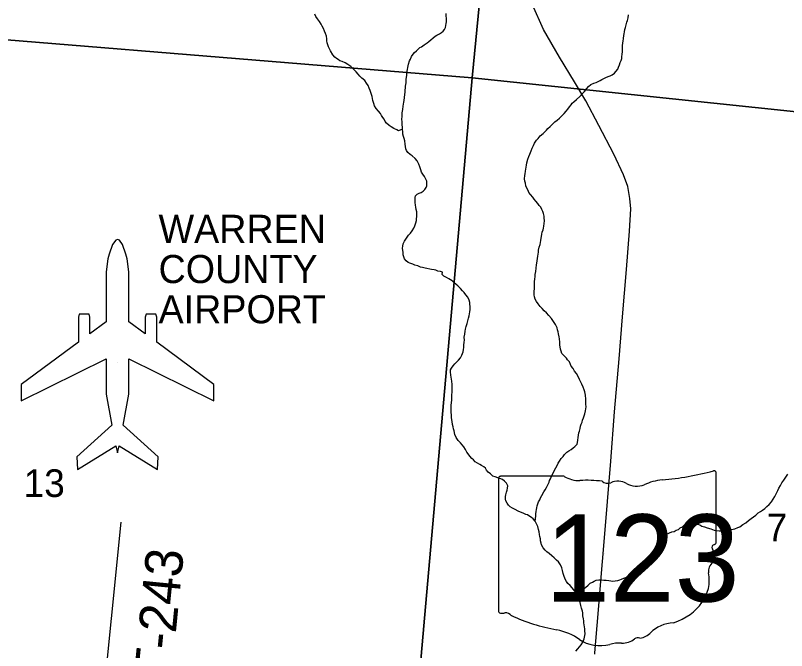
# Model space of a CAD drawing. Extents: x 0 to 1064, y 0 to 440.
# Drawn here: x 203.09 to 221.76, y 263.3 to 278.69 of the extents above; entities that cross this region are included whole.
import ezdxf

# ---------------------------------------------------------------- set-up
doc = ezdxf.new("R2010")
doc.units = 0
for name, color, linetype in [('GM_X_Airport_Class_2', 7, 'Continuous'), ('GM_X_Airport_Location_Class_2', 7, 'Continuous'), ('GM_X_Airport_Text_Class_2', 7, 'Continuous'), ('GM_X_Minor_River', 7, 'Continuous'), ('GM_X_Section', 7, 'Continuous'), ('GM_X_Section_Text', 7, 'Continuous'), ('GM_X_State_Location', 7, 'Continuous'), ('GM_X_State_Route', 7, 'Continuous'), ('GM_X_State_Shield', 7, 'Continuous'), ('GM_X_Township_Road', 7, 'Continuous'), ('GM_X_Township_Road_Text', 7, 'Continuous')]:
    doc.layers.add(name, color=color, linetype=linetype)

msp = doc.modelspace()

# ---------------------------------------------------------------- linework, layer by layer
at = {"layer": 'GM_X_Airport_Class_2'}
msp.add_lwpolyline([(204.616, 270.769), (203.233, 269.747), (203.233, 269.354), (205.29, 270.368), (205.29, 269.514), (205.427, 268.759), (204.58, 267.999), (204.594, 267.686), (205.521, 268.261), (205.564, 268.093), (205.606, 268.261), (206.534, 267.686), (206.547, 267.999), (205.7, 268.759), (205.837, 269.514), (205.837, 270.368), (207.895, 269.354), (207.895, 269.747), (206.512, 270.769), (206.512, 271.38), (206.49, 271.454), (206.255, 271.454), (206.233, 271.38), (206.233, 270.975), (205.837, 271.268), (205.837, 271.268), (205.837, 272.474), (205.797, 272.793), (205.764, 272.906), (205.682, 273.138), (205.607, 273.242), (205.564, 273.26), (205.521, 273.242), (205.445, 273.138), (205.363, 272.906), (205.33, 272.793), (205.29, 272.474), (205.29, 271.268), (204.894, 270.975), (204.894, 271.38), (204.873, 271.454), (204.637, 271.454), (204.616, 271.38)], close=True, dxfattribs=at)
at = {"layer": 'GM_X_Airport_Location_Class_2'}
msp.add_line((205.564, 270.282), (205.564, 270.282), dxfattribs=at)
at = {"layer": 'GM_X_Minor_River'}
for points in [[(212.462, 275.927), (212.364, 275.888), (212.322, 275.913), (212.25, 275.946), (212.184, 275.99), (212.137, 276.016), (212.078, 276.073), (212.042, 276.116), (212.014, 276.172), (211.985, 276.215), (211.956, 276.265), (211.927, 276.314), (211.88, 276.37), (211.828, 276.432), (211.787, 276.494), (211.765, 276.55), (211.743, 276.623), (211.732, 276.672), (211.728, 276.721), (211.706, 276.794), (211.678, 276.868), (211.655, 276.923), (211.633, 276.985), (211.592, 277.047), (211.546, 277.109), (211.48, 277.166), (211.427, 277.216), (211.392, 277.259), (211.339, 277.322), (211.28, 277.378), (211.21, 277.447), (211.138, 277.498), (211.073, 277.536), (211.001, 277.569), (210.946, 277.589), (210.905, 277.62), (210.863, 277.646), (210.821, 277.678), (210.774, 277.728), (210.717, 277.827), (210.671, 277.925), (210.655, 277.974), (210.638, 278.023), (210.633, 278.066), (210.629, 278.121), (210.619, 278.182), (210.597, 278.249), (210.574, 278.305), (210.552, 278.372), (210.517, 278.422), (210.495, 278.471), (210.454, 278.539), (210.401, 278.601), (210.367, 278.657), (210.338, 278.712)], [(212.809, 273.871), (212.805, 273.931), (212.794, 273.986), (212.784, 274.041), (212.773, 274.09), (212.769, 274.151), (212.765, 274.2), (212.767, 274.273), (212.775, 274.315), (212.819, 274.356), (212.868, 274.379), (212.917, 274.401), (212.961, 274.431), (213.005, 274.472), (213.031, 274.519), (213.051, 274.561), (213.047, 274.628), (213.048, 274.671), (213.02, 274.738), (212.997, 274.788), (212.95, 274.838), (212.921, 274.893), (212.905, 274.948), (212.883, 275.022), (212.855, 275.083), (212.815, 275.164), (212.768, 275.22), (212.697, 275.283), (212.649, 275.314), (212.59, 275.365), (212.555, 275.414), (212.544, 275.457), (212.534, 275.512), (212.524, 275.567), (212.514, 275.646), (212.504, 275.707), (212.487, 275.75), (212.471, 275.812), (212.467, 275.866), (212.462, 275.927), (212.458, 275.976), (212.454, 276.037), (212.45, 276.11), (212.446, 276.171), (212.454, 276.237), (212.456, 276.286), (212.457, 276.328), (212.466, 276.407), (212.481, 276.485), (212.489, 276.54), (212.49, 276.582), (212.498, 276.624), (212.506, 276.697), (212.515, 276.769), (212.522, 276.824), (212.524, 276.884), (212.532, 276.927), (212.533, 276.969), (212.541, 277.011), (212.548, 277.054), (212.55, 277.096), (212.551, 277.139), (212.559, 277.181), (212.567, 277.235), (212.568, 277.284), (212.576, 277.332), (212.583, 277.374), (212.591, 277.423), (212.598, 277.465), (212.606, 277.507), (212.633, 277.585), (212.653, 277.627), (212.679, 277.687), (212.723, 277.746), (212.755, 277.788), (212.799, 277.829), (212.837, 277.87), (212.881, 277.906), (212.924, 277.928), (212.987, 277.969), (213.055, 278.022), (213.099, 278.057), (213.149, 278.098), (213.205, 278.144), (213.249, 278.179), (213.293, 278.208), (213.355, 278.237), (213.404, 278.272), (213.448, 278.301), (213.48, 278.348), (213.5, 278.396), (213.514, 278.445), (213.515, 278.487), (213.523, 278.529), (213.525, 278.602), (213.521, 278.681), (213.517, 278.73)], [(217.629, 277.328), (217.674, 277.381), (217.694, 277.435), (217.714, 277.489), (217.728, 277.543), (217.754, 277.597), (217.768, 277.645), (217.775, 277.688), (217.777, 277.736), (217.785, 277.809), (217.788, 277.888), (217.79, 277.948), (217.798, 278.021), (217.8, 278.063), (217.814, 278.124), (217.822, 278.196), (217.83, 278.238), (217.838, 278.287), (217.846, 278.341), (217.859, 278.395), (217.874, 278.456), (217.894, 278.522), (217.908, 278.564), (217.922, 278.63), (217.93, 278.697)], [(215.653, 272.059), (215.655, 272.119), (215.657, 272.186), (215.659, 272.247), (215.667, 272.289), (215.675, 272.368), (215.677, 272.41), (215.691, 272.482), (215.7, 272.567), (215.709, 272.646), (215.71, 272.688), (215.724, 272.742), (215.726, 272.797), (215.734, 272.858), (215.742, 272.906), (215.75, 272.954), (215.757, 273.003), (215.772, 273.075), (215.792, 273.141), (215.806, 273.183), (215.814, 273.238), (215.822, 273.292), (215.829, 273.334), (215.837, 273.389), (215.845, 273.437), (215.865, 273.491), (215.872, 273.533), (215.88, 273.582), (215.894, 273.648), (215.897, 273.715), (215.893, 273.781), (215.888, 273.824), (215.878, 273.885), (215.861, 273.94), (215.832, 273.984), (215.81, 274.045), (215.769, 274.083), (215.734, 274.132), (215.687, 274.189), (215.652, 274.232), (215.617, 274.288), (215.564, 274.35), (215.523, 274.4), (215.5, 274.443), (215.472, 274.499), (215.45, 274.56), (215.439, 274.621), (215.423, 274.67), (215.418, 274.725), (215.421, 274.81), (215.429, 274.852), (215.437, 274.913), (215.444, 274.961), (215.458, 275.009), (215.466, 275.063), (215.474, 275.118), (215.495, 275.202), (215.516, 275.268), (215.542, 275.328), (215.575, 275.406), (215.601, 275.472), (215.634, 275.538), (215.66, 275.592), (215.705, 275.663), (215.743, 275.705), (215.794, 275.77), (215.869, 275.828), (215.945, 275.905), (215.982, 275.946), (216.039, 275.999), (216.089, 276.052), (216.152, 276.105), (216.208, 276.152), (216.265, 276.198), (216.315, 276.251), (216.372, 276.31), (216.423, 276.37), (216.461, 276.417), (216.505, 276.47), (216.543, 276.518), (216.569, 276.559), (216.613, 276.594), (216.676, 276.653), (216.751, 276.724), (216.82, 276.794), (216.864, 276.842), (216.922, 276.913), (216.966, 276.96), (217.022, 277.013), (217.096, 277.047), (217.152, 277.063), (217.195, 277.086), (217.245, 277.109), (217.288, 277.132), (217.338, 277.161), (217.387, 277.184), (217.443, 277.206), (217.492, 277.223), (217.535, 277.246), (217.591, 277.287), (217.629, 277.328)], [(213.651, 268.945), (213.647, 269.018), (213.636, 269.061), (213.638, 269.116), (213.64, 269.176), (213.642, 269.243), (213.644, 269.31), (213.652, 269.37), (213.655, 269.437), (213.657, 269.498), (213.665, 269.564), (213.667, 269.631), (213.664, 269.704), (213.665, 269.746), (213.655, 269.825), (213.651, 269.88), (213.641, 269.929), (213.63, 269.972), (213.62, 270.051), (213.622, 270.106), (213.648, 270.147), (213.692, 270.201), (213.73, 270.248), (213.774, 270.295), (213.818, 270.336), (213.863, 270.396), (213.901, 270.455), (213.915, 270.497), (213.929, 270.54), (213.936, 270.594), (213.944, 270.642), (213.946, 270.697), (213.955, 270.775), (213.962, 270.824), (213.958, 270.891), (213.967, 270.969), (213.975, 271.036), (213.989, 271.084), (214.004, 271.15), (214.024, 271.223), (214.045, 271.289), (214.059, 271.355), (214.073, 271.409), (214.087, 271.457), (214.094, 271.506), (214.102, 271.56), (214.099, 271.639), (214.095, 271.694), (214.09, 271.737), (214.073, 271.786), (214.039, 271.86), (213.998, 271.915), (213.951, 271.972), (213.91, 272.015), (213.863, 272.071), (213.799, 272.134), (213.757, 272.172), (213.704, 272.216), (213.662, 272.254), (213.585, 272.305), (213.525, 272.337), (213.459, 272.369), (213.418, 272.413), (213.426, 272.467), (213.384, 272.481), (213.317, 272.495), (213.269, 272.515), (213.227, 272.522), (213.166, 272.536), (213.124, 272.543), (213.051, 272.558), (213.009, 272.565), (212.943, 272.579), (212.9, 272.593), (212.834, 272.619), (212.762, 272.64), (212.708, 272.66), (212.642, 272.686), (212.6, 272.705), (212.552, 272.743), (212.511, 272.793), (212.495, 272.842), (212.478, 272.891), (212.474, 272.952), (212.469, 272.995), (212.465, 273.05), (212.466, 273.098), (212.481, 273.158), (212.507, 273.218), (212.539, 273.266), (212.577, 273.319), (212.603, 273.361), (212.653, 273.414), (212.692, 273.467), (212.737, 273.533), (212.757, 273.587), (212.783, 273.659), (212.798, 273.719), (212.799, 273.768), (212.807, 273.81), (212.809, 273.871)], [(215.669, 266.436), (215.691, 266.563), (215.693, 266.618), (215.695, 266.672), (215.702, 266.721), (215.71, 266.763), (215.724, 266.811), (215.737, 266.859), (215.751, 266.907), (215.783, 266.955), (215.803, 267.003), (215.835, 267.063), (215.881, 267.146), (215.919, 267.194), (215.951, 267.253), (215.978, 267.319), (216.01, 267.379), (216.024, 267.421), (216.043, 267.463), (216.057, 267.505), (216.077, 267.547), (216.115, 267.619), (216.135, 267.66), (216.174, 267.726), (216.206, 267.786), (216.233, 267.846), (216.265, 267.893), (216.303, 267.953), (216.347, 268.006), (216.386, 268.053), (216.436, 268.106), (216.486, 268.141), (216.542, 268.176), (216.592, 268.217), (216.635, 268.246), (216.686, 268.299), (216.7, 268.347), (216.707, 268.396), (216.716, 268.462), (216.724, 268.517), (216.732, 268.577), (216.745, 268.619), (216.76, 268.685), (216.774, 268.74), (216.787, 268.788), (216.807, 268.836), (216.821, 268.884), (216.847, 268.944), (216.861, 268.992), (216.875, 269.04), (216.889, 269.112), (216.903, 269.161), (216.905, 269.203), (216.901, 269.27), (216.902, 269.312), (216.899, 269.391), (216.89, 269.489), (216.874, 269.568), (216.863, 269.617), (216.835, 269.685), (216.801, 269.759), (216.778, 269.802), (216.75, 269.87), (216.716, 269.943), (216.675, 270.012), (216.629, 270.074), (216.594, 270.135), (216.547, 270.192), (216.525, 270.235), (216.502, 270.296), (216.455, 270.346), (216.432, 270.389), (216.367, 270.446), (216.32, 270.502), (216.304, 270.551), (216.287, 270.6), (216.277, 270.661), (216.272, 270.704), (216.268, 270.771), (216.265, 270.856), (216.254, 270.905), (216.239, 270.978), (216.228, 271.027), (216.217, 271.07), (216.207, 271.119), (216.167, 271.199), (216.12, 271.273), (216.068, 271.348), (216.003, 271.416), (215.945, 271.485), (215.892, 271.535), (215.845, 271.585), (215.791, 271.636), (215.745, 271.698), (215.704, 271.754), (215.676, 271.815), (215.653, 271.87), (215.649, 271.919), (215.65, 271.968), (215.652, 272.016), (215.653, 272.059)], [(216.869, 263.88), (216.858, 263.928), (216.854, 263.977), (216.849, 264.026), (216.845, 264.069), (216.829, 264.148), (216.825, 264.215), (216.821, 264.258), (216.792, 264.331), (216.776, 264.392), (216.76, 264.466), (216.732, 264.539), (216.709, 264.583), (216.693, 264.638), (216.653, 264.718), (216.6, 264.78), (216.565, 264.824), (216.518, 264.88), (216.465, 264.93), (216.43, 264.98), (216.396, 265.036), (216.368, 265.121), (216.351, 265.171), (216.336, 265.244), (216.319, 265.305), (216.285, 265.379), (216.239, 265.453), (216.192, 265.497), (216.133, 265.554), (216.079, 265.598), (216.008, 265.655), (215.955, 265.699), (215.913, 265.737), (215.866, 265.793), (215.826, 265.861), (215.821, 265.903), (215.805, 265.959), (215.8, 266.007), (215.79, 266.068), (215.78, 266.117), (215.77, 266.178), (215.753, 266.239), (215.737, 266.307), (215.709, 266.374), (215.669, 266.436), (215.628, 266.498), (215.586, 266.53), (215.545, 266.555), (215.491, 266.594), (215.449, 266.601), (215.383, 266.633), (215.316, 266.654), (215.262, 266.68), (215.185, 266.718), (215.125, 266.751), (215.071, 266.789), (215.03, 266.826), (214.995, 266.876), (214.966, 266.932), (214.956, 266.974), (214.958, 267.035), (214.965, 267.077), (214.979, 267.144), (214.993, 267.192), (215.007, 267.24), (215.009, 267.295), (214.981, 267.362), (214.933, 267.406), (214.88, 267.444), (214.814, 267.471), (214.772, 267.49), (214.705, 267.51), (214.645, 267.53), (214.592, 267.581), (214.539, 267.625), (214.498, 267.675), (214.469, 267.718), (214.427, 267.756), (214.374, 267.788), (214.332, 267.807), (214.278, 267.839), (214.224, 267.877), (214.177, 267.921), (214.136, 267.959), (214.095, 268.009), (214.048, 268.065), (214.019, 268.108), (213.984, 268.17), (213.944, 268.238), (213.903, 268.288), (213.862, 268.332), (213.809, 268.394), (213.763, 268.462), (213.728, 268.536), (213.713, 268.622), (213.697, 268.677), (213.686, 268.72), (213.67, 268.781), (213.66, 268.848), (213.655, 268.891), (213.651, 268.945)], [(216.653, 264.718), (216.813, 264.762), (216.888, 264.832), (216.957, 264.891), (217.007, 264.938), (217.057, 264.961), (217.1, 264.984), (217.15, 265.006), (217.211, 265.017), (217.278, 265.021), (217.333, 265.013), (217.393, 265.011), (217.46, 265.003), (217.502, 264.995), (217.545, 264.988), (217.606, 264.992), (217.673, 265.002), (217.722, 265.019), (217.765, 265.03), (217.821, 265.058), (217.864, 265.075), (217.92, 265.104), (217.97, 265.133), (218.038, 265.167), (218.081, 265.196), (218.131, 265.225), (218.181, 265.26), (218.231, 265.301), (218.275, 265.336), (218.331, 265.371), (218.381, 265.411), (218.431, 265.459), (218.475, 265.494), (218.531, 265.546), (218.582, 265.612), (218.608, 265.666), (218.628, 265.72), (218.636, 265.78), (218.644, 265.828), (218.652, 265.871), (218.659, 265.919), (218.691, 265.967), (218.723, 266.014), (218.773, 266.055), (218.817, 266.09), (218.861, 266.125), (218.923, 266.154), (218.984, 266.176), (219.04, 266.186), (219.089, 266.221), (219.139, 266.238), (219.183, 266.273), (219.238, 266.302), (219.282, 266.343), (219.344, 266.377), (219.387, 266.388), (219.436, 266.393), (219.497, 266.391), (219.557, 266.377), (219.606, 266.363), (219.66, 266.349), (219.708, 266.318), (219.774, 266.303), (219.84, 266.277), (219.925, 266.25), (220.003, 266.224), (220.063, 266.216), (220.124, 266.208), (220.191, 266.206), (220.24, 266.204), (220.307, 266.214), (220.368, 266.218), (220.429, 266.235), (220.503, 266.251), (220.583, 266.285), (220.627, 266.301), (220.701, 266.354), (220.77, 266.394), (220.838, 266.453), (220.901, 266.505), (220.957, 266.546), (221.013, 266.587), (221.07, 266.64), (221.126, 266.675), (221.176, 266.703), (221.232, 266.744), (221.282, 266.791), (221.339, 266.844), (221.395, 266.909), (221.434, 266.969), (221.473, 267.034), (221.505, 267.1), (221.544, 267.178), (221.571, 267.238), (221.609, 267.303), (221.642, 267.369), (221.693, 267.428), (221.738, 267.5), (221.789, 267.577)], [(216.661, 263.291), (216.705, 263.344), (216.743, 263.392), (216.788, 263.445), (216.826, 263.511), (216.859, 263.588), (216.874, 263.667), (216.882, 263.709), (216.878, 263.782), (216.873, 263.831), (216.869, 263.88)]]:
    msp.add_lwpolyline(points, dxfattribs=at)
at = {"layer": 'GM_X_Section'}
for points in [[(215.966, 295.854), (214.149, 277.17), (197.538, 278.526), (198.919, 293.248)], [(232.294, 291.87), (230.695, 275.436), (214.149, 277.17), (215.966, 295.854)], [(214.149, 277.17), (212.38, 257.134), (197.008, 258.503), (195.61, 258.628), (197.538, 278.526)], [(230.695, 275.436), (228.85, 255.88), (213.239, 257.045), (212.38, 257.134), (214.149, 277.17)]]:
    msp.add_lwpolyline(points, close=True, dxfattribs=at)
at = {"layer": 'GM_X_State_Route'}
msp.add_lwpolyline([(217.117, 263.217), (217.119, 263.247), (217.196, 264.193), (217.263, 264.982), (217.34, 265.935), (217.424, 266.911), (217.501, 267.888), (217.596, 269.083), (217.705, 270.369), (217.79, 271.388), (217.884, 272.535), (217.96, 273.463), (217.991, 274.003), (217.967, 274.253), (217.919, 274.546), (217.81, 274.828), (217.578, 275.326), (217.217, 276.021), (216.896, 276.618), (216.627, 277.074), (216.263, 277.672), (215.877, 278.344), (215.61, 278.945)], dxfattribs=at)
at = {"layer": 'GM_X_State_Shield'}
for p, q in [((216.378, 267.524), (214.834, 267.524)), ((220.055, 265.928), (220.055, 267.603)), ((214.782, 267.468), (214.782, 264.267)), ((220.055, 265.928), (220.055, 265.928))]:
    msp.add_line(p, q, dxfattribs=at)
for centre, major_axis, start_param, end_param in [((214.842, 267.475), (0.0611, 0), 1.712693, 3.28349), ((216.746, 267.895), (0.593, 0), 4.042523, 4.731795), ((218.177, 271.889), (5.592, 0), 4.814394, 5.042369), ((219.997, 267.61), (0.0587, 0), 6.141152, 7.989035), ((216.942, 265.726), (2.127, 0), 1.404758, 1.657858), ((217.425, 267.492), (0.171, 0), 3.836095, 5.185415), ((217.676, 267.122), (0.355, 0), 0.950623, 2.079405), ((218.135, 267.629), (0.428, 0), 4.081561, 5.145723), ((218.89, 266.546), (1.125, 0), 1.699011, 2.107814), ((220.042, 265.805), (0.0909, 0), 1.883978, 3.671073), ((219.993, 265.921), (0.0628, 0), 5.05454, 6.418171), ((219.464, 265.593), (0.545, 0), 5.934695, 6.695948), ((220.266, 265.227), (0.397, 0), 2.387724, 3.262537), ((218.49, 265.014), (1.399, 0), 5.101752, 6.440018), ((214.843, 264.26), (0.0616, 0), 3.00124, 4.508301), ((214.852, 264.587), (0.47, 0), 4.665946, 4.897461), ((214.949, 264.082), (0.17, 0), 0.519207, 1.627899), ((217.09, 266.959), (4.038, 0), 4.195997, 4.488961), ((219.08, 263.368), (0.766, 0), 1.647645, 2.488434), ((215.886, 262.828), (1.264, 0), 0.823519, 1.323587), ((218.161, 263.516), (0.12, 0), 1.147584, 2.315152), ((218.109, 263.956), (0.452, 0), 4.937069, 5.64225), ((217.252, 264.066), (0.802, 0), 4.026481, 4.996735), ((217.716, 262.959), (0.659, 0), 1.495662, 1.94098), ((217.774, 263.826), (0.427, 0), 4.691044, 5.507374)]:
    msp.add_ellipse(centre, major_axis=major_axis, ratio=0.8, start_param=start_param, end_param=end_param, dxfattribs=at)
at = {"layer": 'GM_X_Township_Road'}
msp.add_lwpolyline([(205.18, 261.746), (205.649, 266.411)], dxfattribs=at)

# ---------------------------------------------------------------- texts
at = {"layer": 'GM_X_Airport_Text_Class_2'}
for s, p in [('WARREN', (206.556, 273.176)), ('COUNTY', (206.556, 272.203)), ('AIRPORT', (206.556, 271.229))]:
    msp.add_text(s, height=0.6818, rotation=0, dxfattribs=at).set_placement(p)
at = {"layer": 'GM_X_Section_Text'}
for s, height, p in [('13', 0.6697, (203.29, 267.024)), ('7', 0.67, (221.276, 265.946))]:
    msp.add_text(s, height=height, rotation=0, dxfattribs=at).set_placement(p)
at = {"layer": 'GM_X_State_Location'}
for s in ['s', 'r']:
    msp.add_text(s, height=0.00303, dxfattribs=at).set_placement((217.359, 265.655))
msp.add_text('123', height=0.00303, rotation=0, dxfattribs=at).set_placement((216.29, 265.434))
at = {"layer": 'GM_X_State_Shield'}
msp.add_text('123', height=2.1094, dxfattribs=at).set_placement((215.913, 264.492))
at = {"layer": 'GM_X_Township_Road_Text'}
msp.add_text('T-243', height=0.9091, rotation=84.3732, dxfattribs=at).set_placement((206.86, 262.568))

doc.saveas('drawing.dxf')
